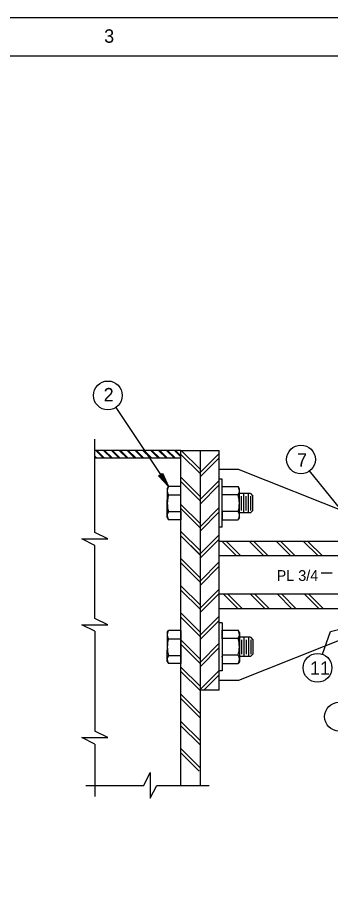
# Model space of a CAD drawing. Extents: x 0.1 to 13.5, y 0.1 to 9.5.
# Drawn here: x 6.543 to 7.902, y 5.677 to 9.457 of the extents above; entities that cross this region are included whole.
import ezdxf

# ---------------------------------------------------------------- set-up
doc = ezdxf.new("R2010")
doc.units = 0
for name, color, linetype in [('Level 1', 7, 'Continuous'), ('Level 2', 7, 'Continuous'), ('Level 25', 7, 'Continuous'), ('Level 3', 7, 'Continuous'), ('Level 44', 7, 'Continuous')]:
    doc.layers.add(name, color=color, linetype=linetype)

msp = doc.modelspace()

# ---------------------------------------------------------------- linework, layer by layer
at = {"layer": 'Level 1'}
for points in [[(0.1238, 9.4569), (13.4571, 9.4569), (13.4571, 0.1236), (0.1238, 0.1236)], [(0.6238, 9.2903), (13.2904, 9.2903), (13.2904, 0.2903), (0.6238, 0.2903)]]:
    msp.add_lwpolyline(points, close=True, dxfattribs=at)
for points in [[(6.8784, 7.1634), (6.8222, 7.1913), (6.9346, 7.1913), (6.8784, 7.2195)], [(6.8784, 6.7902), (6.8222, 6.8181), (6.9346, 6.8181), (6.8784, 6.8463)], [(6.8784, 6.3006), (6.8222, 6.3285), (6.9346, 6.3285), (6.8784, 6.3566)], [(7.0914, 6.1211), (7.1193, 6.1774), (7.1193, 6.065), (7.1474, 6.1211)]]:
    msp.add_lwpolyline(points, dxfattribs=at)
at = {"layer": 'Level 2'}
for p, q in [((6.8784, 7.2195), (6.8784, 7.6252)), ((7.252, 7.5761), (6.8784, 7.5761)), ((7.252, 6.1211), (7.252, 7.5761)), ((7.3353, 7.5761), (7.3353, 6.1211)), ((7.252, 7.5422), (6.8784, 7.5422)), ((7.502, 7.4927), (7.4186, 7.4927)), ((7.4319, 7.4506), (7.4189, 7.4506)), ((7.4319, 7.2423), (7.4319, 7.4506)), ((7.1934, 7.4094), (7.199, 7.4191)), ((7.1934, 7.4094), (7.1934, 7.3614)), ((7.252, 7.4191), (7.199, 7.4191)), ((7.252, 7.2747), (7.252, 7.4191)), ((7.4319, 7.4187), (7.5005, 7.4187)), ((7.5061, 7.409), (7.5005, 7.4187)), ((7.5061, 7.2839), (7.5061, 7.409)), ((7.1989, 7.3831), (7.252, 7.3831)), ((7.5006, 7.3826), (7.4319, 7.3826)), ((7.5543, 7.3883), (7.5061, 7.3883)), ((7.5152, 7.3152), (7.5152, 7.3774)), ((7.5256, 7.3047), (7.5256, 7.3883)), ((7.5361, 7.3152), (7.5361, 7.3774)), ((7.5465, 7.3047), (7.5465, 7.3883)), ((7.5543, 7.3883), (7.5647, 7.3779)), ((7.5565, 7.3157), (7.5565, 7.3779)), ((7.5647, 7.3151), (7.5647, 7.3779)), ((7.5647, 7.3151), (7.5647, 7.3779)), ((7.1934, 7.3469), (7.1934, 7.3614)), ((7.1934, 7.2844), (7.1934, 7.3469)), ((7.1989, 7.3107), (7.252, 7.3107)), ((7.252, 7.3112), (7.252, 7.2747)), ((7.4319, 7.3108), (7.4319, 7.2743)), ((7.5006, 7.3103), (7.4319, 7.3103)), ((7.5543, 7.3047), (7.5061, 7.3047)), ((7.5543, 7.3047), (7.5647, 7.3151)), ((7.1934, 7.2844), (7.199, 7.2747)), ((7.252, 7.2747), (7.199, 7.2747)), ((7.4319, 7.2743), (7.5005, 7.2743)), ((7.5061, 7.2839), (7.5005, 7.2743)), ((7.4319, 7.2423), (7.4189, 7.2423)), ((8.0247, 7.1802), (7.4186, 7.1802)), ((8.0247, 7.1177), (7.4186, 7.1177)), ((8.0247, 6.9511), (7.4186, 6.9511)), ((8.0247, 6.8886), (7.4186, 6.8886)), ((7.4319, 6.8265), (7.4189, 6.8265)), ((7.4319, 6.8265), (7.4319, 6.6181)), ((6.8784, 6.7902), (6.8784, 6.3566)), ((7.1934, 6.7844), (7.199, 6.7941)), ((7.1934, 6.7844), (7.1934, 6.7219)), ((7.252, 6.7941), (7.199, 6.7941)), ((7.252, 6.7941), (7.252, 6.6497)), ((7.252, 6.7576), (7.252, 6.7941)), ((7.4319, 6.758), (7.4319, 6.7945)), ((7.4319, 6.7945), (7.5005, 6.7945)), ((7.5061, 6.7848), (7.5005, 6.7945)), ((7.5061, 6.7848), (7.5061, 6.6597)), ((7.1989, 6.7581), (7.252, 6.7581)), ((7.2546, 6.7637), (7.252, 6.7637)), ((7.4293, 6.7641), (7.4319, 6.7641)), ((7.5006, 6.7585), (7.4319, 6.7585)), ((7.5543, 6.7641), (7.5061, 6.7641)), ((7.5152, 6.7535), (7.5152, 6.6913)), ((7.5256, 6.7641), (7.5256, 6.6804)), ((7.5361, 6.7535), (7.5361, 6.6913)), ((7.5465, 6.7641), (7.5465, 6.6804)), ((7.5543, 6.7641), (7.5647, 6.7536)), ((7.5565, 6.7531), (7.5565, 6.6908)), ((7.5647, 6.7536), (7.5647, 6.6909)), ((7.5647, 6.7536), (7.5647, 6.6909)), ((7.1934, 6.7219), (7.1934, 6.709)), ((7.1934, 6.6594), (7.1934, 6.709)), ((7.5543, 6.6804), (7.5647, 6.6909)), ((7.1934, 6.6594), (7.199, 6.6497)), ((7.1989, 6.6857), (7.252, 6.6857)), ((7.2546, 6.6801), (7.252, 6.6801)), ((7.4293, 6.6804), (7.4319, 6.6804)), ((7.5006, 6.6861), (7.4319, 6.6861)), ((7.5061, 6.6597), (7.5005, 6.6501)), ((7.5543, 6.6804), (7.5061, 6.6804)), ((7.252, 6.6497), (7.199, 6.6497)), ((7.4319, 6.6181), (7.4189, 6.6181)), ((7.4319, 6.6501), (7.5005, 6.6501)), ((7.502, 6.5761), (7.4186, 6.5761)), ((7.4186, 6.5344), (7.3353, 6.5344)), ((6.8784, 6.3006), (6.8784, 6.0729)), ((6.8394, 6.1211), (7.0914, 6.1211))]:
    msp.add_line(p, q, dxfattribs=at)
for points in [[(7.3353, 7.4942), (7.2534, 7.5761)], [(7.3353, 7.4799), (7.4186, 7.5632)], [(7.3353, 7.4754), (7.252, 7.5587)], [(7.3353, 7.4611), (7.4186, 7.5444)], [(7.3353, 7.3764), (7.252, 7.4597)], [(7.3353, 7.3575), (7.252, 7.4408)], [(7.3353, 7.3621), (7.4186, 7.4454)], [(7.3353, 7.3432), (7.4186, 7.4265)], [(7.3353, 7.2585), (7.252, 7.3418)], [(7.3353, 7.2396), (7.252, 7.323)], [(7.3353, 7.2442), (7.4186, 7.3275)], [(7.3353, 7.2254), (7.4186, 7.3087)], [(7.3353, 7.1407), (7.252, 7.224)], [(7.3353, 7.1218), (7.252, 7.2051)], [(7.3353, 7.1264), (7.4186, 7.2097)], [(7.3353, 7.1075), (7.4186, 7.1908)], [(7.3389, 7.1182), (7.2764, 7.1807)], [(7.4928, 7.1192), (7.4303, 7.1817)], [(7.5116, 7.1192), (7.4491, 7.1817)], [(7.6121, 7.1177), (7.5496, 7.1802)], [(7.6295, 7.1192), (7.567, 7.1817)], [(7.7297, 7.1177), (7.6672, 7.1802)], [(7.7485, 7.1177), (7.686, 7.1802)], [(7.8475, 7.1177), (7.785, 7.1802)], [(7.8664, 7.1177), (7.8039, 7.1802)], [(7.3353, 7.0228), (7.252, 7.1061)], [(7.3353, 7.0039), (7.252, 7.0873)], [(7.3353, 7.0085), (7.4186, 7.0918)], [(7.3353, 6.9897), (7.4186, 7.073)], [(7.3353, 6.905), (7.252, 6.9883)], [(7.3353, 6.8861), (7.252, 6.9694)], [(7.3353, 6.8907), (7.4186, 6.974)], [(7.3353, 6.8718), (7.4186, 6.9551)], [(7.5006, 6.8874), (7.4381, 6.9499)], [(7.5195, 6.8874), (7.457, 6.9499)], [(7.6185, 6.8874), (7.556, 6.9499)], [(7.6373, 6.8874), (7.5749, 6.9499)], [(7.734, 6.8886), (7.6715, 6.9511)], [(7.7529, 6.8886), (7.6904, 6.9511)], [(7.8519, 6.8886), (7.7894, 6.9511)], [(7.8707, 6.8886), (7.8083, 6.9511)], [(7.3353, 6.7871), (7.252, 6.8704)], [(7.3353, 6.7683), (7.252, 6.8516)], [(7.3353, 6.7728), (7.4186, 6.8561)], [(7.3353, 6.754), (7.4186, 6.8373)], [(7.3353, 6.6693), (7.252, 6.7526)], [(7.3353, 6.6504), (7.252, 6.7337)], [(7.3353, 6.655), (7.4186, 6.7383)], [(7.3353, 6.6361), (7.4186, 6.7194)], [(7.3353, 6.5514), (7.252, 6.6347)], [(7.3353, 6.5326), (7.252, 6.6159)], [(7.3353, 6.5371), (7.4186, 6.6204)], [(7.3514, 6.5344), (7.4186, 6.6016)], [(7.3353, 6.4336), (7.252, 6.5169)], [(7.3353, 6.4147), (7.252, 6.498)], [(7.3353, 6.3157), (7.252, 6.399)], [(7.3353, 6.2968), (7.252, 6.3802)], [(7.3353, 6.1979), (7.252, 6.2812)], [(7.3321, 6.1822), (7.252, 6.2623)]]:
    msp.add_lwpolyline(points, dxfattribs=at)
for centre, radius, start, end in [((7.2247, 7.4009), 0.0314, 149.7124, 214.511), ((7.4748, 7.4004), 0.0314, 325.489, 30.2876), ((7.3189, 7.3464), 0.1255, 163.0196, 173.1312), ((7.3806, 7.346), 0.1255, 343.5034, 16.9816), ((7.3189, 7.3464), 0.1255, 173.1312, 179.7886), ((7.3189, 7.3464), 0.1255, 179.7886, 196.4948), ((7.2247, 7.293), 0.0314, 145.489, 210.2876), ((7.4748, 7.2925), 0.0314, 329.7124, 34.511), ((7.2247, 6.7758), 0.0314, 149.7124, 214.511), ((7.4748, 6.7762), 0.0314, 325.489, 30.2876), ((7.3189, 6.7224), 0.1255, 163.5052, 180.2114), ((7.3806, 6.7228), 0.1255, 343.0184, 16.4966), ((7.3189, 6.7224), 0.1255, 180.2114, 186.1219), ((7.3189, 6.7224), 0.1255, 186.1219, 196.9804), ((7.2247, 6.668), 0.0314, 145.489, 210.2876), ((7.4748, 6.6683), 0.0314, 329.7124, 34.511)]:
    msp.add_arc(centre, radius, start, end, dxfattribs=at)
at = {"layer": 'Level 25'}
for p, q in [((7.252, 7.5761), (7.3353, 7.5761)), ((7.3353, 7.5761), (7.4186, 7.5761)), ((7.4186, 6.5344), (7.4186, 7.5761)), ((8.0247, 7.2844), (7.502, 7.4927)), ((8.0256, 7.2212), (7.8111, 7.4878)), ((6.8784, 6.8463), (6.8784, 7.1634)), ((8.0247, 6.7844), (7.502, 6.5761)), ((7.1474, 6.1211), (7.3757, 6.1211))]:
    msp.add_line(p, q, dxfattribs=at)
at = {"layer": 'Level 3'}
for p, q in [((6.9702, 7.7629), (7.199, 7.4191)), ((7.1894, 7.4336), (7.1894, 7.4336)), ((7.199, 7.4191), (7.199, 7.4191)), ((7.8612, 7.0436), (7.9082, 7.0436)), ((7.9012, 6.7892), (8.0753, 6.8321)), ((7.8663, 6.6908), (7.9012, 6.7892))]:
    msp.add_line(p, q, dxfattribs=at)
msp.add_lwpolyline([(7.1731, 7.4767), (7.199, 7.4191), (7.1559, 7.4653), (7.1706, 7.4751), (7.1894, 7.4336), (7.1601, 7.4649), (7.1696, 7.4712), (7.1802, 7.4474), (7.1644, 7.4645), (7.1683, 7.4671), (7.1706, 7.4619)], dxfattribs=at)
for centre in [(6.9355, 7.8149), (7.7734, 7.5366), (7.8454, 6.6319), (7.9384, 6.4193)]:
    msp.add_circle(centre, 0.0625, dxfattribs=at)
at = {"layer": 'Level 44'}
for p, q in [((6.9164, 7.5422), (6.8825, 7.5761)), ((6.9211, 7.5422), (6.8872, 7.5761)), ((6.9506, 7.5422), (6.9167, 7.5761)), ((6.9553, 7.5422), (6.9214, 7.5761)), ((6.9847, 7.5422), (6.9509, 7.5761)), ((6.9894, 7.5422), (6.9556, 7.5761)), ((7.0189, 7.5422), (6.9851, 7.5761)), ((7.0236, 7.5422), (6.9898, 7.5761)), ((7.0531, 7.5422), (7.0192, 7.5761)), ((7.0578, 7.5422), (7.0239, 7.5761)), ((7.0873, 7.5422), (7.0534, 7.5761)), ((7.092, 7.5422), (7.0581, 7.5761)), ((7.1214, 7.5422), (7.0876, 7.5761)), ((7.1262, 7.5422), (7.0923, 7.5761)), ((7.1556, 7.5422), (7.1218, 7.5761)), ((7.1603, 7.5422), (7.1265, 7.5761)), ((7.1898, 7.5422), (7.1559, 7.5761)), ((7.1945, 7.5422), (7.1607, 7.5761)), ((7.224, 7.5422), (7.1901, 7.5761)), ((7.2287, 7.5422), (7.1948, 7.5761)), ((7.252, 7.5484), (7.2243, 7.5761)), ((7.252, 7.5531), (7.229, 7.5761)), ((6.8869, 7.5422), (6.8784, 7.5507)), ((6.8822, 7.5422), (6.8784, 7.546))]:
    msp.add_line(p, q, dxfattribs=at)

# ---------------------------------------------------------------- texts
at = {"layer": 'Level 1'}
msp.add_text('3', height=0.0584, dxfattribs=at).set_placement((6.9193, 9.3467))
at = {"layer": 'Level 3'}
for s, height, p in [('2', 0.0583, (6.9172, 7.7889)), ('7', 0.0583, (7.7566, 7.505)), ('PL 3/4', 0.04667, (7.6681, 7.0092)), ('11', 0.05833, (7.8127, 6.6012))]:
    msp.add_text(s, height=height, dxfattribs=at).set_placement(p)

doc.saveas('drawing.dxf')
